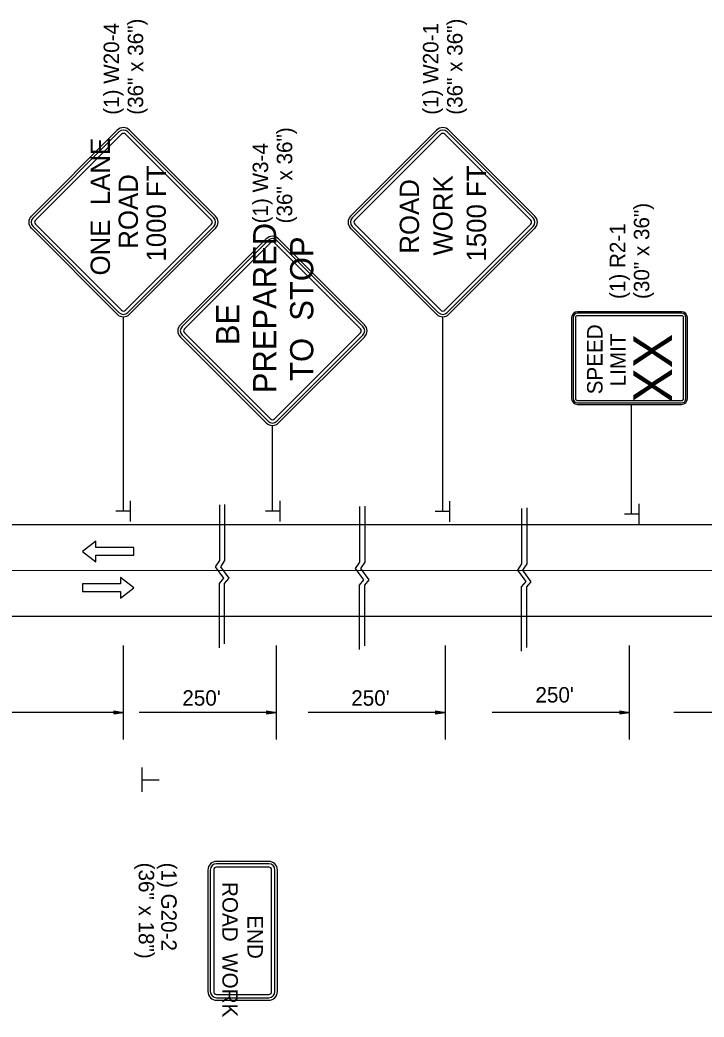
# Model space of a CAD drawing. Extents: x 1930579 to 1939784, y 596179 to 597522.
# Drawn here: x 1937686.1 to 1937952, y 596310.9 to 596698.7 of the extents above; entities that cross this region are included whole.
import ezdxf

# ---------------------------------------------------------------- set-up
doc = ezdxf.new("R2010")
doc.units = 0
for name, color, linetype in [('Default', 7, 'Continuous'), ('P_TC_Signs_Permanent', 7, 'Continuous'), ('P_TC_Signs_Temporary', 7, 'Continuous'), ('R_Annotation', 7, 'Continuous'), ('R_Striping', 7, 'Continuous')]:
    doc.layers.add(name, color=color, linetype=linetype)

msp = doc.modelspace()

# ---------------------------------------------------------------- linework, layer by layer
at = {"layer": 'Default'}
for p, q in [((1937728.97, 596511.65), (1937728.97, 596503.64)), ((1937787.07, 596511.65), (1937787.07, 596503.64)), ((1937853.08, 596511.55), (1937853.08, 596503.54)), ((1937926.62, 596510.52), (1937926.62, 596502.51)), ((1937728.85, 596507.67), (1937723.39, 596507.67)), ((1937786.95, 596507.67), (1937781.49, 596507.67)), ((1937852.96, 596507.57), (1937847.5, 596507.57)), ((1937926.5, 596506.54), (1937921.04, 596506.54)), ((1937444.6, 596502.47), (1938059.31, 596502.42)), ((1937443.89, 596484.68), (1938161.51, 596484.63)), ((1937444.38, 596466.89), (1938059.31, 596466.85)), ((1937726.35, 596418.83), (1937726.35, 596455.43)), ((1937785.8, 596418.83), (1937785.8, 596455.43)), ((1937851.46, 596418.83), (1937851.46, 596455.43)), ((1937923.05, 596418.83), (1937923.05, 596455.43)), ((1937726.35, 596429.42), (1937626.6, 596429.42)), ((1937722.51, 596429.99), (1937726.35, 596429.42)), ((1937722.51, 596429.99), (1937722.51, 596428.84)), ((1937722.51, 596429.9), (1937725.71, 596429.42)), ((1937722.51, 596429.8), (1937725.05, 596429.42)), ((1937722.51, 596429.7), (1937724.41, 596429.42)), ((1937722.51, 596429.6), (1937723.76, 596429.42)), ((1937722.51, 596429.51), (1937723.12, 596429.42)), ((1937722.51, 596428.84), (1937726.35, 596429.42)), ((1937722.51, 596429.23), (1937723.76, 596429.42)), ((1937722.51, 596429.04), (1937725.05, 596429.42)), ((1937722.51, 596428.94), (1937725.71, 596429.42)), ((1937722.51, 596429.13), (1937724.41, 596429.42)), ((1937722.51, 596429.33), (1937723.12, 596429.42)), ((1937785.8, 596429.42), (1937732.4, 596429.42)), ((1937781.97, 596429.99), (1937785.8, 596429.42)), ((1937781.97, 596429.99), (1937781.97, 596428.84)), ((1937781.97, 596429.9), (1937785.16, 596429.42)), ((1937781.97, 596429.8), (1937784.5, 596429.42)), ((1937781.97, 596429.7), (1937783.87, 596429.42)), ((1937781.97, 596429.6), (1937783.21, 596429.42)), ((1937781.97, 596429.51), (1937782.57, 596429.42)), ((1937781.97, 596428.84), (1937785.8, 596429.42)), ((1937781.97, 596429.23), (1937783.21, 596429.42)), ((1937781.97, 596429.04), (1937784.5, 596429.42)), ((1937781.97, 596428.94), (1937785.16, 596429.42)), ((1937781.97, 596429.13), (1937783.87, 596429.42)), ((1937781.97, 596429.33), (1937782.57, 596429.42)), ((1937851.46, 596429.42), (1937798.06, 596429.42)), ((1937847.62, 596429.99), (1937851.46, 596429.42)), ((1937847.62, 596429.99), (1937847.62, 596428.84)), ((1937847.62, 596429.9), (1937850.82, 596429.42)), ((1937847.62, 596429.8), (1937850.16, 596429.42)), ((1937847.62, 596429.7), (1937849.52, 596429.42)), ((1937847.62, 596429.6), (1937848.87, 596429.42)), ((1937847.62, 596429.51), (1937848.23, 596429.42)), ((1937847.62, 596428.84), (1937851.46, 596429.42)), ((1937847.62, 596429.23), (1937848.87, 596429.42)), ((1937847.62, 596429.04), (1937850.16, 596429.42)), ((1937847.62, 596428.94), (1937850.82, 596429.42)), ((1937847.62, 596429.13), (1937849.52, 596429.42)), ((1937847.62, 596429.33), (1937848.23, 596429.42)), ((1937923.05, 596429.42), (1937869.65, 596429.42)), ((1937919.21, 596429.99), (1937923.05, 596429.42)), ((1937919.21, 596429.99), (1937919.21, 596428.84)), ((1937919.21, 596429.9), (1937922.41, 596429.42)), ((1937919.21, 596429.8), (1937921.75, 596429.42)), ((1937919.21, 596429.7), (1937921.11, 596429.42)), ((1937919.21, 596429.6), (1937920.46, 596429.42)), ((1937919.21, 596429.51), (1937919.82, 596429.42)), ((1937919.21, 596428.84), (1937923.05, 596429.42)), ((1937919.21, 596429.23), (1937920.46, 596429.42)), ((1937919.21, 596429.04), (1937921.75, 596429.42)), ((1937919.21, 596428.94), (1937922.41, 596429.42)), ((1937919.21, 596429.13), (1937921.11, 596429.42)), ((1937919.21, 596429.33), (1937919.82, 596429.42)), ((1937993.66, 596429.42), (1937940.26, 596429.42)), ((1937733.61, 596398.51), (1937733.61, 596408)), ((1937733.75, 596403.23), (1937740.23, 596403.23))]:
    msp.add_line(p, q, dxfattribs=at)
for points in [[(1937763.59, 596510.05), (1937763.59, 596488.53), (1937761.92, 596486.06), (1937765.16, 596481.63), (1937763.46, 596479.58), (1937763.45, 596454.56)], [(1937765.63, 596510.25), (1937765.63, 596488.44), (1937763.97, 596485.97), (1937767.21, 596481.54), (1937765.5, 596479.5), (1937765.5, 596456)], [(1937818.05, 596509.41), (1937818.05, 596487.88), (1937816.39, 596485.41), (1937819.62, 596480.98), (1937817.92, 596478.94), (1937817.91, 596453.91)], [(1937820.09, 596509.6), (1937820.09, 596487.8), (1937818.43, 596485.33), (1937821.67, 596480.9), (1937819.96, 596478.85), (1937819.96, 596455.35)], [(1937881.09, 596508.73), (1937881.09, 596487.21), (1937879.43, 596484.74), (1937882.67, 596480.31), (1937880.96, 596478.27), (1937880.96, 596453.24)], [(1937883.13, 596508.93), (1937883.13, 596487.13), (1937881.47, 596484.65), (1937884.71, 596480.23), (1937883.01, 596478.18), (1937883, 596454.68)]]:
    msp.add_lwpolyline(points, dxfattribs=at)
at = {"layer": 'P_TC_Signs_Permanent'}
for p, q in [((1937781.83, 596613.56), (1937748.42, 596580.15)), ((1937820.02, 596580.15), (1937786.61, 596613.56)), ((1937782.5, 596612.89), (1937749.08, 596579.48)), ((1937783.42, 596611.97), (1937750.01, 596578.56)), ((1937818.43, 596578.56), (1937785.01, 596611.97)), ((1937819.35, 596579.48), (1937785.94, 596612.89)), ((1937900.52, 596582.91), (1937900.52, 596551.41)), ((1937901.08, 596582.91), (1937901.08, 596551.41)), ((1937902.02, 596582.91), (1937902.02, 596551.41)), ((1937943.27, 596585.16), (1937902.77, 596585.16)), ((1937943.27, 596584.59), (1937902.77, 596584.59)), ((1937943.27, 596583.66), (1937902.77, 596583.66)), ((1937944.02, 596551.41), (1937944.02, 596582.91)), ((1937944.96, 596551.41), (1937944.96, 596582.91)), ((1937945.52, 596551.41), (1937945.52, 596582.91)), ((1937748.42, 596575.37), (1937781.83, 596541.96)), ((1937749.08, 596576.04), (1937782.5, 596542.63)), ((1937750.01, 596576.96), (1937783.42, 596543.55)), ((1937785.01, 596543.55), (1937818.43, 596576.96)), ((1937785.94, 596542.63), (1937819.35, 596576.04)), ((1937786.61, 596541.96), (1937820.02, 596575.37)), ((1937902.77, 596550.66), (1937943.27, 596550.66)), ((1937902.77, 596549.72), (1937943.27, 596549.72)), ((1937902.77, 596549.16), (1937943.27, 596549.16))]:
    msp.add_line(p, q, dxfattribs=at)
for centre, radius, start, end in [((1937784.22, 596611.17), 3.38, 45, 135), ((1937784.22, 596611.17), 2.44, 45, 135), ((1937784.22, 596611.17), 1.13, 45, 135), ((1937902.77, 596582.91), 2.25, 90, 180), ((1937902.77, 596582.91), 1.69, 90, 180), ((1937902.77, 596582.91), 0.75, 90, 180), ((1937943.27, 596582.91), 2.25, 360, 90), ((1937943.27, 596582.91), 1.69, 360, 90), ((1937943.27, 596582.91), 0.75, 360, 90), ((1937750.81, 596577.76), 3.38, 135, 225), ((1937750.81, 596577.76), 2.44, 135, 225), ((1937750.81, 596577.76), 1.13, 135, 225), ((1937817.63, 596577.76), 1.13, 315, 45), ((1937817.63, 596577.76), 2.44, 315, 45), ((1937817.63, 596577.76), 3.38, 315, 45), ((1937902.77, 596551.41), 2.25, 180, 270), ((1937902.77, 596551.41), 1.69, 180, 270), ((1937902.77, 596551.41), 0.75, 180, 270), ((1937943.27, 596551.41), 2.25, 270, 360), ((1937943.27, 596551.41), 1.69, 270, 360), ((1937943.27, 596551.41), 0.75, 270, 360), ((1937784.22, 596544.35), 1.13, 225, 315), ((1937784.22, 596544.35), 3.38, 225, 315), ((1937784.22, 596544.35), 2.44, 225, 315)]:
    msp.add_arc(centre, radius, start, end, dxfattribs=at)
at = {"layer": 'P_TC_Signs_Temporary'}
for p, q in [((1937690.5, 596622.4), (1937723.91, 596655.81)), ((1937728.68, 596655.81), (1937762.09, 596622.4)), ((1937814.61, 596622.4), (1937848.02, 596655.81)), ((1937852.79, 596655.81), (1937886.2, 596622.4)), ((1937691.16, 596621.74), (1937724.57, 596655.15)), ((1937692.09, 596620.81), (1937725.5, 596654.22)), ((1937727.09, 596654.22), (1937760.5, 596620.81)), ((1937728.02, 596655.15), (1937761.43, 596621.74)), ((1937815.27, 596621.74), (1937848.68, 596655.15)), ((1937816.2, 596620.81), (1937849.61, 596654.22)), ((1937851.2, 596654.22), (1937884.61, 596620.81)), ((1937852.13, 596655.15), (1937885.54, 596621.74)), ((1937723.91, 596584.22), (1937690.5, 596617.63)), ((1937724.57, 596584.88), (1937691.16, 596618.29)), ((1937725.5, 596585.81), (1937692.09, 596619.22)), ((1937760.5, 596619.22), (1937727.09, 596585.81)), ((1937761.43, 596618.29), (1937728.02, 596584.88)), ((1937762.09, 596617.63), (1937728.68, 596584.22)), ((1937848.02, 596584.22), (1937814.61, 596617.63)), ((1937848.68, 596584.88), (1937815.27, 596618.29)), ((1937849.61, 596585.81), (1937816.2, 596619.22)), ((1937884.61, 596619.22), (1937851.2, 596585.81)), ((1937885.54, 596618.29), (1937852.13, 596584.88)), ((1937886.2, 596617.63), (1937852.79, 596584.22)), ((1937782.76, 596371.49), (1937762.51, 596371.49)), ((1937782.76, 596370.55), (1937762.51, 596370.55)), ((1937782.76, 596369.24), (1937762.51, 596369.24)), ((1937759.13, 596368.11), (1937759.13, 596320.86)), ((1937760.07, 596368.11), (1937760.07, 596320.86)), ((1937761.38, 596368.11), (1937761.38, 596320.86)), ((1937783.88, 596320.86), (1937783.88, 596368.11)), ((1937785.2, 596320.86), (1937785.2, 596368.11)), ((1937786.13, 596320.86), (1937786.13, 596368.11)), ((1937762.51, 596319.74), (1937782.76, 596319.74)), ((1937762.51, 596318.43), (1937782.76, 596318.43)), ((1937762.51, 596317.49), (1937782.76, 596317.49))]:
    msp.add_line(p, q, dxfattribs=at)
for centre, radius, start, end in [((1937726.29, 596653.42), 3.38, 45, 135), ((1937726.29, 596653.42), 2.44, 45, 135), ((1937850.41, 596653.42), 3.38, 45, 135), ((1937850.41, 596653.42), 2.44, 45, 135), ((1937726.29, 596653.42), 1.12, 45, 135), ((1937850.41, 596653.42), 1.12, 45, 135), ((1937692.88, 596620.01), 3.38, 135, 225), ((1937692.88, 596620.01), 2.44, 135, 225), ((1937759.7, 596620.01), 2.44, 315, 45), ((1937759.7, 596620.01), 3.38, 315, 45), ((1937816.99, 596620.01), 3.38, 135, 225), ((1937816.99, 596620.01), 2.44, 135, 225), ((1937883.82, 596620.01), 2.44, 315, 45), ((1937883.82, 596620.01), 3.38, 315, 45), ((1937692.88, 596620.01), 1.13, 135, 225), ((1937759.7, 596620.01), 1.13, 315, 45), ((1937816.99, 596620.01), 1.13, 135, 225), ((1937883.82, 596620.01), 1.13, 315, 45), ((1937726.29, 596586.6), 3.38, 225, 315), ((1937726.29, 596586.6), 2.44, 225, 315), ((1937726.29, 596586.6), 1.12, 225, 315), ((1937850.41, 596586.6), 3.38, 225, 315), ((1937850.41, 596586.6), 2.44, 225, 315), ((1937850.41, 596586.6), 1.12, 225, 315), ((1937762.51, 596368.11), 3.38, 90, 180), ((1937762.51, 596368.11), 2.44, 90, 180), ((1937762.51, 596368.11), 1.13, 90, 180), ((1937782.76, 596368.11), 3.38, 360, 90), ((1937782.76, 596368.11), 2.44, 360, 90), ((1937782.76, 596368.11), 1.13, 360, 90), ((1937762.51, 596320.86), 3.38, 180, 270), ((1937762.51, 596320.86), 2.44, 180, 270), ((1937762.51, 596320.86), 1.13, 180, 270), ((1937782.76, 596320.86), 2.44, 270, 360), ((1937782.76, 596320.86), 1.13, 270, 360), ((1937782.76, 596320.86), 3.38, 270, 360)]:
    msp.add_arc(centre, radius, start, end, dxfattribs=at)
at = {"layer": 'R_Annotation'}
for p, q in [((1937726.29, 596507.67), (1937726.29, 596583.23)), ((1937850.41, 596507.57), (1937850.41, 596583.23)), ((1937923.77, 596506.54), (1937923.77, 596549.16)), ((1937784.22, 596507.67), (1937784.22, 596540.97))]:
    msp.add_line(p, q, dxfattribs=at)
at = {"layer": 'R_Striping'}
for points in [[(1937715.62, 596495.98), (1937710.43, 596491.98), (1937715.62, 596487.98), (1937715.62, 596490.48), (1937730.33, 596490.48), (1937730.33, 596493.48), (1937715.62, 596493.48)], [(1937725.14, 596473.85), (1937730.33, 596477.85), (1937725.14, 596481.85), (1937725.14, 596479.35), (1937710.43, 596479.35), (1937710.43, 596476.35), (1937725.14, 596476.35)]]:
    msp.add_lwpolyline(points, close=True, dxfattribs=at)

# ---------------------------------------------------------------- texts
at = {"layer": 'Default'}
for p in [(1937886.45, 596433.25), (1937749.2, 596432.02), (1937814.86, 596432.02)]:
    msp.add_text("250'", height=6, rotation=360, dxfattribs=at).set_placement(p)
at = {"layer": 'P_TC_Signs_Permanent'}
for s, height, p in [('SPEED', 6, (1937912.52, 596553.09)), ('LIMIT', 6, (1937921.52, 596556.18)), ('XX', 15, (1937939.52, 596549.86))]:
    msp.add_text(s, height=height, rotation=90, dxfattribs=at).set_placement(p)
at = {"layer": 'P_TC_Signs_Temporary'}
for s, height, rotation, p in [('ONE  LANE', 7.5, 90, (1937721.04, 596599.31)), ('1000 FT', 7.5, 90, (1937742.79, 596604.72)), ('1500 FT', 7.5, 90, (1937867.24, 596604.72)), ('ROAD', 7.5, 90, (1937731.92, 596609.71)), ('WORK', 7.5, 90, (1937854.22, 596607.02)), (' ROAD ', 7.5, 90, (1937841.19, 596604.99)), ('PREPARED', 9, 90, (1937785.69, 596553.52)), ('TO  STOP', 9, 90, (1937800.09, 596558.3)), ('BE', 9, 90, (1937771.29, 596572.21)), ('ROAD  WORK', 6, 270, (1937764.76, 596363.45)), ('END', 6, 270, (1937774.51, 596350.52))]:
    msp.add_text(s, height=height, rotation=rotation, dxfattribs=at).set_placement(p)
at = {"layer": 'R_Annotation'}
for s, height, rotation, p in [('(36" x 36")', 5.9996, 90, (1937733.97, 596661.8)), ('(36" x 36")', 5.9996, 90, (1937858.09, 596661.8)), ('(1) W20-4', 6, 90, (1937724.61, 596661.8)), ('(1) W20-1', 6, 90, (1937848.72, 596661.8)), ('(36" x 36")', 5.9996, 90, (1937791.9, 596619.55)), ('(1) W3-4', 6, 90, (1937782.54, 596619.55)), ('(30" x 36")', 5.9996, 90, (1937930.7, 596590.16)), ('(1) R2-1', 6, 90, (1937921.34, 596590.16)), ('(36" x 18")', 5.9996, 270, (1937732.23, 596370.98)), ('(1) G20-2', 6, 270, (1937740.98, 596370.98))]:
    msp.add_text(s, height=height, rotation=rotation, dxfattribs=at).set_placement(p)

doc.saveas('drawing.dxf')
